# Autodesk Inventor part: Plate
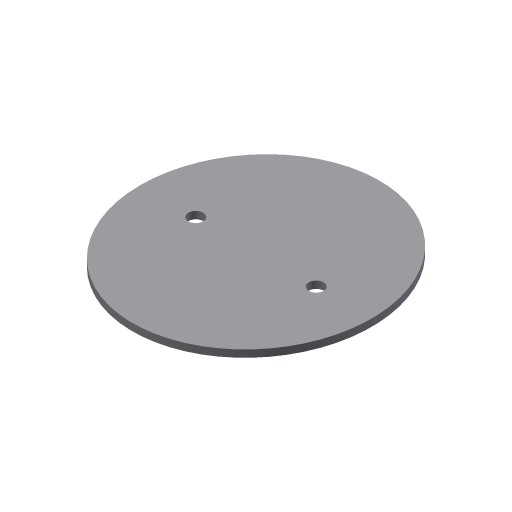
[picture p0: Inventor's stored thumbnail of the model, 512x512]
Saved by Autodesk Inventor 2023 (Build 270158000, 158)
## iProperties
Created: 2009-04
Part Number: Plate
Document SubType Name: Modeling
Designer: Sham
Density: 1 g/cm^3
Material: Generic
Appearance: Default
Author: Sham
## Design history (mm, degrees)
sketch "Sketch1"
  geometry: C1 r 6.25 at (-50, 0); C2 r 6.25 at (50, 0); 4 further points
  constraints: 2 centre point, 1 coincident, 5 other
  dimensions: "d1" = 12.5 diameter of C1; "d2" = 12.5 diameter of C2; "d3" = 100 distance of C2.centre C1.centre; "d4" = 102.5 distance of point (0, 0) point (0, 102.5); "d5" = 96 distance of point (0, 0) point (-96, 0); "d6" = 50 distance of point (0, 0) C1.centre
extrude "Extrusion1" new body sketch "Sketch1" distance "d7" = 6; taper "d8" = 0 deg
body "Solid1"
